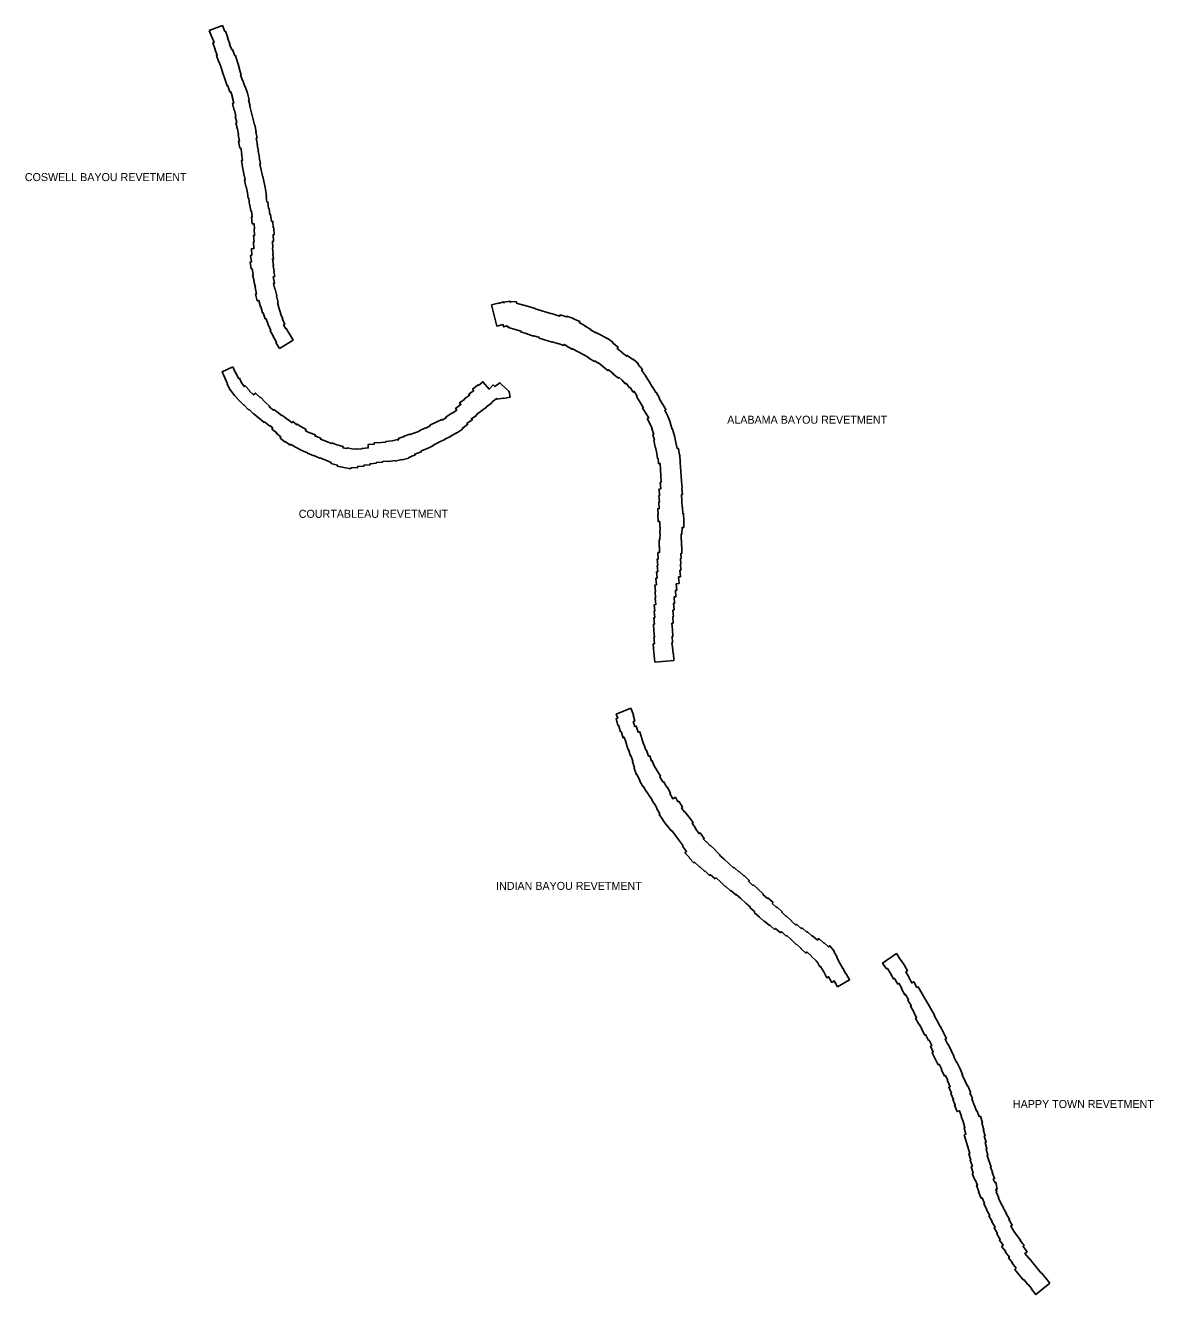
# Model space of a CAD drawing. Extents: x 2650582 to 3923188, y 277893 to 989177.
# Drawn here: x 3148250 to 3170810, y 691107 to 716490 of the extents above; entities that cross this region are included whole.
import ezdxf

# ---------------------------------------------------------------- set-up
doc = ezdxf.new("R2010")
doc.units = 0
doc.layers.add('Level 3', color=7, linetype='Continuous')

msp = doc.modelspace()

# ---------------------------------------------------------------- linework, layer by layer
at = {"layer": 'Level 3'}
for points in [[(3151925, 716388), (3152192, 716490)], [(3153333, 710027), (3153259, 710146), (3153274, 710156), (3153205, 710266), (3153213, 710270), (3153144, 710381), (3153160, 710391), (3153105, 710510), (3153106, 710511), (3153061, 710624), (3153045, 710619), (3153004, 710743), (3152989, 710739), (3152958, 710865), (3152948, 710862), (3152916, 710989), (3152885, 710981), (3152851, 711117), (3152872, 711122), (3152841, 711249), (3152849, 711251), (3152818, 711377), (3152822, 711378), (3152791, 711502), (3152802, 711505), (3152783, 711622), (3152765, 711619), (3152743, 711757), (3152771, 711762), (3152751, 711890), (3152779, 711895), (3152770, 712022), (3152818, 712026), (3152809, 712155), (3152823, 712156), (3152814, 712286), (3152832, 712287), (3152823, 712416), (3152829, 712417), (3152821, 712523), (3152787, 712519), (3152770, 712658), (3152786, 712660), (3152772, 712777), (3152755, 712775), (3152739, 712904), (3152732, 712903), (3152716, 713032), (3152707, 713031), (3152694, 713139), (3152690, 713138), (3152665, 713266), (3152660, 713265), (3152634, 713403), (3152643, 713405), (3152621, 713522), (3152618, 713521), (3152590, 713658), (3152594, 713659), (3152569, 713787), (3152593, 713791), (3152568, 713918), (3152577, 713920), (3152555, 714038), (3152541, 714035), (3152514, 714173), (3152531, 714176), (3152506, 714304), (3152513, 714306), (3152492, 714415), (3152459, 714541), (3152480, 714546), (3152446, 714671), (3152460, 714675), (3152429, 714791), (3152424, 714790), (3152388, 714925), (3152417, 714933), (3152384, 715058), (3152389, 715060), (3152355, 715163), (3152341, 715159), (3152301, 715282), (3152287, 715278), (3152246, 715401), (3152243, 715400), (3152200, 715534), (3152201, 715534), (3152165, 715647), (3152162, 715646), (3152126, 715757), (3152121, 715756), (3152071, 715887), (3152085, 715892), (3152039, 716014), (3152044, 716015), (3151998, 716137), (3152023, 716147), (3151980, 716259), (3151975, 716256), (3151925, 716388)], [(3152192, 716490), (3152239, 716368), (3152248, 716372), (3152298, 716241), (3152294, 716239), (3152340, 716118), (3152334, 716115), (3152377, 716003), (3152388, 716008), (3152437, 715882), (3152450, 715886), (3152493, 715753), (3152492, 715752), (3152531, 715630), (3152524, 715628), (3152564, 715504), (3152552, 715501), (3152589, 715386), (3152597, 715389), (3152637, 715265), (3152646, 715268), (3152689, 715135), (3152688, 715134), (3152723, 715004), (3152711, 715001), (3152744, 714875), (3152735, 714873), (3152834, 714500), (3152839, 714501), (3152866, 714364), (3152857, 714362), (3152882, 714235), (3152866, 714232), (3152890, 714104), (3152884, 714102), (3152908, 713975), (3152904, 713974), (3152928, 713846), (3152923, 713845), (3152948, 713718), (3152939, 713716), (3152962, 713598), (3152967, 713599), (3152992, 713472), (3153000, 713474), (3153050, 713214), (3153054, 713214), (3153071, 713075), (3153064, 713074), (3153079, 712955), (3153098, 712958), (3153114, 712829), (3153122, 712830), (3153138, 712703), (3153152, 712705), (3153168, 712571), (3153196, 712573), (3153205, 712443), (3153216, 712444), (3153225, 712305), (3153204, 712303), (3153213, 712173), (3153190, 712171), (3153200, 712042), (3153192, 712041), (3153201, 711912), (3153197, 711911), (3153211, 711821), (3153193, 711818), (3153214, 711690), (3153201, 711688), (3153221, 711560), (3153215, 711559), (3153237, 711469), (3153203, 711461), (3153234, 711336), (3153212, 711331), (3153240, 711214), (3153243, 711215), (3153276, 711079), (3153271, 711078), (3153303, 710951), (3153294, 710949), (3153326, 710823), (3153324, 710822), (3153357, 710720), (3153354, 710719), (3153395, 710618), (3153388, 710615), (3153436, 710509), (3153411, 710498), (3153458, 710424), (3153466, 710428), (3153540, 710310), (3153535, 710307), (3153604, 710196), (3153333, 710027)], [(3157569, 710901), (3157705, 710934), (3157706, 710931), (3157816, 710958), (3157821, 710941), (3157818, 710957), (3157941, 710974), (3157945, 710949), (3157946, 710966), (3158070, 710960), (3158068, 710936), (3158186, 710900), (3158187, 710904), (3158311, 710866), (3158311, 710867), (3158445, 710825), (3158444, 710821), (3158558, 710785), (3158559, 710786), (3158683, 710748), (3158684, 710751), (3158808, 710712), (3158809, 710715), (3158809, 710715), (3158933, 710677), (3158940, 710701), (3159072, 710660), (3159077, 710674), (3159208, 710625), (3159208, 710624), (3159334, 710568), (3159326, 710551), (3159446, 710484), (3159440, 710473), (3159554, 710409), (3159549, 710401), (3159654, 710342), (3159658, 710351), (3159763, 710293), (3159764, 710294), (3159881, 710229), (3159885, 710233), (3159999, 710153), (3159991, 710142)], [(3159522, 709844), (3159419, 709901), (3159418, 709899), (3159305, 709962), (3159303, 709959), (3159189, 710022), (3159185, 710014), (3159062, 710082), (3159066, 710089), (3159020, 710110), (3159013, 710091), (3158911, 710128), (3158909, 710123), (3158785, 710160), (3158783, 710153), (3158525, 710232), (3158529, 710247), (3158414, 710282), (3158413, 710277), (3158279, 710318), (3158281, 710323), (3158156, 710361), (3158160, 710375), (3158046, 710411), (3158044, 710406), (3157911, 710447), (3157916, 710464), (3157888, 710460), (3157885, 710479), (3157812, 710461), (3157801, 710506), (3157675, 710475), (3157569, 710901)], [(3159991, 710142), (3160100, 710057), (3160080, 710031), (3160182, 709951), (3160178, 709946), (3160273, 709872), (3160286, 709889), (3160394, 709805), (3160403, 709815), (3160508, 709722), (3160498, 709712), (3160587, 709606), (3160571, 709592), (3160652, 709485), (3160648, 709481), (3160723, 709370), (3160721, 709368), (3160786, 709260), (3160789, 709262), (3160856, 709151), (3160860, 709154), (3160932, 709034), (3160923, 709028), (3161057, 708805), (3161036, 708793), (3161094, 708672), (3161098, 708674), (3161148, 708543), (3161143, 708541), (3161183, 708416), (3161189, 708417), (3161227, 708283), (3161226, 708282), (3161256, 708150), (3161255, 708150), (3161283, 708026), (3161309, 708030), (3161327, 707897), (3161336, 707898), (3161345, 707758), (3161344, 707758), (3161370, 707378), (3161372, 707378), (3161382, 707239), (3161378, 707238), (3161387, 707109), (3161367, 707107), (3161375, 706977), (3161375, 706977), (3161383, 706858), (3161386, 706858), (3161396, 706723), (3161411, 706723), (3161416, 706588), (3161418, 706588), (3161415, 706448), (3161382, 706449), (3161379, 706319), (3161362, 706319), (3161360, 706199), (3161370, 706199), (3161367, 706069), (3161376, 706068), (3161373, 705929), (3161357, 705929), (3161362, 705830), (3161350, 705830), (3161359, 705717), (3161346, 705715)], [(3160962, 707350), (3160953, 707480), (3160958, 707480), (3160949, 707610), (3160950, 707610), (3160942, 707730), (3160909, 707728), (3160902, 707832), (3160890, 707830), (3160877, 707930), (3160848, 708056), (3160845, 708056), (3160814, 708192), (3160827, 708195), (3160796, 708306), (3160814, 708311), (3160776, 708428), (3160780, 708429), (3160752, 708502), (3160747, 708499), (3160686, 708625), (3160713, 708639), (3160664, 708721), (3160662, 708720), (3160590, 708840), (3160603, 708847), (3160536, 708959), (3160537, 708959), (3160470, 709071), (3160481, 709078), (3160426, 709170), (3160406, 709157), (3160342, 709251), (3160330, 709242), (3160261, 709333), (3160245, 709319), (3160183, 709394), (3160120, 709450), (3160109, 709435), (3159999, 709521), (3160004, 709529), (3159910, 709602), (3159898, 709587), (3159788, 709673), (3159791, 709678), (3159711, 709741), (3159705, 709732), (3159638, 709779), (3159632, 709769), (3159516, 709833), (3159522, 709844)], [(3153198, 708439), (3153143, 708482), (3153140, 708478), (3153033, 708561), (3153025, 708551), (3152921, 708637), (3152917, 708632), (3152816, 708722), (3152813, 708719), (3152721, 708811), (3152714, 708804), (3152622, 708896), (3152619, 708893), (3152524, 708988), (3152523, 708988), (3152433, 709088), (3152430, 709086), (3152350, 709195), (3152345, 709193), (3152286, 709320), (3152290, 709322), (3152236, 709440), (3152238, 709441), (3152183, 709559), (3152399, 709659)], [(3152399, 709659), (3152454, 709541), (3152458, 709543), (3152513, 709425), (3152529, 709433), (3152567, 709353), (3152627, 709270), (3152642, 709283), (3152736, 709179), (3152734, 709178), (3152812, 709100), (3152849, 709137), (3152941, 709045), (3152948, 709052), (3153047, 708953), (3153046, 708953), (3153134, 708874), (3153125, 708864), (3153209, 708793), (3153219, 708806), (3153321, 708726), (3153324, 708730), (3153386, 708681)], [(3155693, 708198), (3155714, 708204), (3155706, 708228), (3155825, 708267), (3155821, 708278), (3155939, 708316), (3155942, 708306), (3156034, 708341), (3156035, 708340), (3156128, 708376), (3156125, 708382), (3156253, 708439), (3156254, 708436), (3156343, 708481), (3156337, 708492), (3156462, 708555), (3156463, 708553), (3156575, 708610), (3156582, 708597), (3156670, 708650), (3156662, 708662), (3156780, 708738), (3156784, 708732), (3156876, 708796), (3156852, 708831), (3156959, 708905), (3156932, 708943), (3157034, 709015), (3157030, 709022), (3157132, 709093), (3157117, 709115), (3157216, 709185), (3157193, 709216), (3157305, 709300), (3157312, 709291), (3157399, 709363), (3157522, 709217), (3157606, 709299), (3157637, 709267), (3157738, 709344), (3157760, 709314), (3157922, 709169), (3157916, 709163), (3157924, 709164), (3157946, 709056)], [(3157946, 709056), (3157808, 709030), (3157806, 709038), (3157674, 709013), (3157670, 709030), (3157571, 708946), (3157576, 708940), (3157467, 708859), (3157469, 708856), (3157367, 708784), (3157369, 708781), (3157267, 708709), (3157274, 708698), (3157168, 708624), (3157185, 708599), (3157078, 708525), (3157093, 708505), (3156982, 708427), (3156990, 708414), (3156872, 708338), (3156870, 708342), (3156754, 708272), (3156750, 708278), (3156745, 708276), (3156748, 708269), (3156636, 708212), (3156638, 708208), (3156520, 708153), (3156521, 708152), (3156405, 708098), (3156405, 708097), (3156404, 708096), (3156408, 708087), (3156287, 708031), (3156288, 708029), (3156285, 708028), (3156285, 708026), (3156173, 707981), (3156174, 707978), (3156160, 707973), (3156165, 707959), (3156037, 707913), (3156042, 707896), (3155968, 707873), (3155971, 707865), (3155915, 707847), (3155917, 707838), (3155782, 707801), (3155780, 707807), (3155647, 707777), (3155644, 707786)], [(3153386, 708681), (3153392, 708688), (3153491, 708611), (3153492, 708613), (3153581, 708544), (3153598, 708565), (3153676, 708504), (3153684, 708517), (3153757, 708466), (3153861, 708406), (3153849, 708384), (3153917, 708348), (3153918, 708351), (3154048, 708299), (3154040, 708280), (3154159, 708232), (3154152, 708214), (3154256, 708172), (3154257, 708173), (3154373, 708126), (3154379, 708141), (3154474, 708102), (3154602, 708065), (3154596, 708043), (3154680, 708025), (3154682, 708039), (3154810, 708018), (3154871, 708023), (3154872, 708015), (3154982, 708022), (3154981, 708030), (3155106, 708039), (3155101, 708108), (3155226, 708117), (3155224, 708141), (3155364, 708151), (3155364, 708149), (3155456, 708155), (3155455, 708165), (3155587, 708184), (3155691, 708207), (3155693, 708198)], [(3155644, 707786), (3155511, 707768), (3155510, 707773), (3155391, 707765), (3155391, 707757), (3155266, 707748), (3155268, 707733), (3155143, 707724), (3155144, 707704), (3155019, 707695), (3155021, 707678), (3154896, 707670), (3154897, 707649), (3154760, 707640), (3154757, 707623), (3154619, 707645), (3154619, 707646), (3154486, 707675), (3154490, 707694), (3154360, 707731), (3154366, 707749), (3154255, 707794), (3154139, 707841), (3154138, 707838), (3154019, 707886), (3154017, 707882), (3153888, 707935), (3153890, 707941), (3153775, 707988), (3153775, 707987), (3153651, 708053), (3153652, 708055), (3153553, 708113), (3153542, 708097), (3153443, 708167), (3153439, 708161), (3153341, 708237), (3153359, 708259), (3153270, 708328), (3153279, 708340), (3153180, 708417), (3153198, 708439)], [(3160837, 703757), (3160825, 703886), (3160822, 703886), (3160810, 704025), (3160812, 704025), (3160804, 704120), (3160830, 704122), (3160819, 704252), (3160829, 704253), (3160818, 704382), (3160819, 704383), (3160808, 704512), (3160828, 704514), (3160816, 704643), (3160834, 704645), (3160822, 704774), (3160835, 704775), (3160824, 704905), (3160854, 704907), (3160842, 705037), (3160852, 705038), (3160841, 705167), (3160849, 705168), (3160838, 705297), (3160867, 705300), (3160855, 705429), (3160881, 705432), (3160870, 705561), (3160893, 705563), (3160883, 705685), (3160895, 705686), (3160884, 705815), (3160906, 705817), (3160899, 705946), (3160929, 705948), (3160931, 706066), (3160922, 706067), (3160925, 706207), (3160939, 706206), (3160941, 706327), (3160939, 706327), (3160941, 706457), (3160934, 706457), (3160935, 706567), (3160904, 706566), (3160899, 706705), (3160904, 706706), (3160896, 706824), (3160925, 706826), (3160916, 706955), (3160927, 706956), (3160918, 707086), (3160931, 707087), (3160922, 707217), (3160954, 707219), (3160945, 707348), (3160962, 707350)], [(3161346, 705715), (3161356, 705593), (3161337, 705592), (3161348, 705463), (3161310, 705459), (3161321, 705329), (3161263, 705324), (3161274, 705195), (3161247, 705193), (3161258, 705063), (3161221, 705060), (3161232, 704930), (3161209, 704928), (3161220, 704799), (3161198, 704797), (3161209, 704668), (3161194, 704666), (3161205, 704537), (3161179, 704534), (3161190, 704405), (3161186, 704405), (3161197, 704275), (3161180, 704274), (3161191, 704144), (3161179, 704143), (3161187, 704058), (3161190, 704058), (3161202, 703929), (3161206, 703929), (3161218, 703790), (3160837, 703757)], [(3160355, 702833), (3160063, 702715), (3160095, 702635), (3160062, 702627), (3160096, 702491), (3160107, 702494), (3160149, 702365), (3160160, 702368), (3160200, 702245), (3160226, 702253), (3160263, 702139), (3160261, 702138), (3160304, 702005), (3160312, 702008), (3160352, 701884), (3160357, 701886), (3160394, 701772), (3160387, 701769), (3160429, 701639), (3160420, 701635), (3160472, 701505), (3160474, 701506), (3160538, 701396), (3160529, 701391), (3160599, 701270), (3160604, 701273), (3160669, 701160), (3160676, 701164), (3160741, 701052), (3160747, 701055), (3160812, 700943), (3160813, 700943), (3160873, 700839), (3160870, 700838), (3160938, 700720), (3160925, 700711), (3161001, 700598), (3160998, 700596), (3161083, 700484), (3161085, 700486), (3161163, 700382), (3161173, 700390), (3161251, 700286), (3161252, 700287), (3161325, 700191), (3161323, 700189), (3161401, 700085), (3161390, 700077), (3161470, 699971), (3161439, 699943), (3161528, 699847), (3161524, 699844), (3161619, 699741), (3161631, 699753), (3161731, 699659), (3161733, 699661), (3161828, 699573), (3161836, 699581), (3161931, 699492), (3161945, 699507), (3162040, 699419)], [(3162324, 699723), (3162221, 699818), (3162220, 699817), (3162132, 699898), (3162138, 699905), (3162043, 699994), (3162046, 699997), (3161944, 700093), (3161938, 700086), (3161866, 700163), (3161863, 700160), (3161808, 700218), (3161824, 700230), (3161740, 700341), (3161720, 700326), (3161648, 700422), (3161658, 700430), (3161580, 700533), (3161603, 700551), (3161519, 700663), (3161517, 700662), (3161439, 700765), (3161430, 700758), (3161367, 700841), (3161392, 700858), (3161314, 700974), (3161299, 700964), (3161246, 701054), (3161195, 701025), (3161135, 701129), (3161150, 701138), (3161080, 701259), (3161073, 701255), (3161008, 701367), (3160997, 701361), (3160937, 701465), (3160949, 701472), (3160879, 701593), (3160877, 701592), (3160824, 701685), (3160784, 701782), (3160769, 701776), (3160735, 701882), (3160708, 701874), (3160668, 701997), (3160659, 701995), (3160619, 702118), (3160610, 702115), (3160573, 702229), (3160578, 702231), (3160535, 702364), (3160506, 702355), (3160466, 702478), (3160436, 702469), (3160404, 702568), (3160435, 702576), (3160404, 702702), (3160407, 702703), (3160355, 702833)], [(3164488, 697265), (3164730, 697399), (3164662, 697521), (3164658, 697519), (3164595, 697633), (3164593, 697632), (3164535, 697737), (3164535, 697737), (3164472, 697851), (3164480, 697855), (3164416, 697969), (3164425, 697976), (3164336, 698083), (3164310, 698062), (3164218, 698148), (3164212, 698141), (3164117, 698229), (3164086, 698197), (3163991, 698285), (3163981, 698275), (3163886, 698363), (3163876, 698353), (3163781, 698442), (3163766, 698425), (3163671, 698514), (3163654, 698496), (3163566, 698578), (3163569, 698580), (3163467, 698676), (3163462, 698671), (3163375, 698753), (3163382, 698761), (3163280, 698856), (3163271, 698847), (3163183, 698929), (3163200, 698947), (3163097, 699042), (3163086, 699030), (3162998, 699112), (3163005, 699119), (3162902, 699214), (3162901, 699213), (3162806, 699302), (3162797, 699292), (3162709, 699374), (3162725, 699391), (3162623, 699487), (3162616, 699479), (3162521, 699568), (3162517, 699564), (3162422, 699652), (3162410, 699640), (3162323, 699722), (3162324, 699723)], [(3162040, 699419), (3162061, 699442), (3162149, 699360), (3162149, 699360), (3162251, 699264), (3162257, 699270), (3162352, 699181), (3162358, 699187), (3162453, 699099), (3162465, 699112), (3162553, 699031), (3162553, 699030), (3162655, 698935), (3162658, 698938), (3162746, 698856), (3162739, 698849), (3162834, 698760), (3162825, 698750), (3162928, 698655), (3162929, 698657), (3163024, 698568), (3163030, 698575), (3163126, 698486), (3163137, 698498), (3163232, 698409), (3163252, 698431), (3163348, 698343), (3163369, 698366), (3163464, 698277), (3163476, 698290), (3163563, 698208), (3163562, 698207), (3163665, 698111), (3163669, 698115), (3163756, 698033), (3163755, 698032), (3163857, 697936), (3163878, 697959), (3163966, 697877), (3163964, 697875), (3164060, 697785), (3164094, 697745), (3164138, 697665), (3164150, 697672), (3164213, 697559), (3164214, 697559), (3164277, 697445), (3164310, 697464), (3164373, 697350), (3164425, 697379), (3164488, 697265)], [(3165717, 697333), (3165692, 697318), (3165627, 697431), (3165609, 697420), (3165539, 697542), (3165543, 697545), (3165487, 697630), (3165471, 697619), (3165391, 697733), (3165667, 697927), (3165745, 697816), (3165819, 697703), (3165820, 697704), (3165890, 697583), (3165858, 697564), (3165923, 697451), (3165914, 697446), (3165973, 697342), (3166012, 697364), (3166077, 697251), (3166100, 697265), (3166234, 697031), (3166293, 696926), (3166295, 696927), (3166430, 696693), (3166424, 696690), (3166480, 696580), (3166484, 696582), (3166543, 696466), (3166546, 696468), (3166609, 696343), (3166607, 696342), (3166666, 696226), (3166641, 696214), (3166696, 696107), (3166702, 696110), (3166765, 695985), (3166761, 695983), (3166820, 695867), (3166812, 695863), (3166867, 695755), (3166872, 695759), (3166934, 695636), (3166991, 695508), (3166981, 695504), (3167085, 695276), (3167094, 695280), (3167151, 695153), (3167133, 695144)], [(3167180, 693531), (3167204, 693541), (3167160, 693662), (3167185, 693671), (3167140, 693794), (3167154, 693799), (3167116, 693923), (3167134, 693929), (3167022, 694302), (3167058, 694313), (3167020, 694437), (3167037, 694443), (3166999, 694567), (3167002, 694568), (3167002, 694568), (3166963, 694669), (3166967, 694672), (3166925, 694783), (3166880, 694766), (3166830, 694896), (3166843, 694902), (3166797, 695006), (3166810, 695011), (3166757, 695130), (3166767, 695135), (3166713, 695253), (3166739, 695264), (3166686, 695383), (3166692, 695386), (3166647, 695488), (3166630, 695479), (3166567, 695604), (3166573, 695607), (3166519, 695714), (3166500, 695704), (3166379, 695945), (3166404, 695958), (3166345, 696074), (3166374, 696089), (3166320, 696196), (3166309, 696190), (3166250, 696306), (3166232, 696297), (3166169, 696422), (3166172, 696424), (3166124, 696517), (3166117, 696513), (3166047, 696634), (3166071, 696648), (3166006, 696761), (3166013, 696764), (3165948, 696877), (3165963, 696886), (3165898, 696998), (3165910, 697005), (3165850, 697109), (3165838, 697102), (3165768, 697224), (3165776, 697228), (3165717, 697333)], [(3167133, 695144), (3167185, 695026), (3167176, 695021), (3167266, 694785), (3167277, 694789), (3167324, 694666), (3167347, 694673), (3167388, 694539), (3167378, 694536), (3167415, 694412), (3167403, 694408), (3167440, 694283), (3167422, 694278), (3167460, 694153), (3167440, 694147), (3167478, 694023), (3167459, 694017), (3167497, 693893), (3167479, 693887), (3167560, 693659), (3167548, 693655), (3167591, 693554), (3167580, 693549), (3167631, 693429), (3167604, 693418), (3167634, 693348), (3167657, 693353), (3167681, 693215), (3167654, 693210), (3167673, 693165), (3167662, 693160), (3167713, 693040), (3167706, 693038), (3167756, 692935), (3167754, 692934), (3167808, 692845), (3167804, 692842), (3167871, 692731), (3167861, 692725), (3167928, 692614), (3167916, 692607), (3167983, 692495), (3167952, 692476), (3168017, 692376), (3168014, 692374), (3168081, 692283), (3168079, 692281), (3168149, 692194), (3168140, 692186), (3168221, 692086), (3168198, 692067), (3168279, 691965), (3168235, 691930), (3168312, 691837), (3168315, 691840), (3168562, 691537), (3168566, 691541), (3168735, 691334)], [(3168735, 691334), (3168455, 691107), (3168367, 691216), (3168373, 691221), (3168298, 691312), (3168296, 691310), (3168214, 691410), (3168202, 691401), (3168033, 691612), (3168060, 691634), (3167979, 691735), (3167991, 691745), (3167909, 691846), (3167925, 691859), (3167844, 691960), (3167852, 691966), (3167770, 692068), (3167802, 692093), (3167726, 692198), (3167744, 692211), (3167673, 692320), (3167686, 692329), (3167619, 692440), (3167640, 692453), (3167573, 692564), (3167584, 692571), (3167517, 692682), (3167534, 692692), (3167467, 692804), (3167473, 692807), (3167416, 692925), (3167426, 692930), (3167379, 693040), (3167363, 693033), (3167308, 693162), (3167318, 693166), (3167267, 693286), (3167286, 693294), (3167240, 693404), (3167234, 693402), (3167180, 693531)]]:
    msp.add_lwpolyline(points, dxfattribs=at)

# ---------------------------------------------------------------- texts
for s, p in [('COSWELL BAYOU REVETMENT', (3148239, 713376)), ('ALABAMA BAYOU REVETMENT', (3162283, 708524)), ('COURTABLEAU REVETMENT', (3153716, 706642)), ('INDIAN BAYOU REVETMENT', (3157662, 699201)), ('HAPPY TOWN REVETMENT', (3167997, 694839))]:
    msp.add_text(s, height=160, dxfattribs=at).set_placement(p)

doc.saveas('drawing.dxf')
